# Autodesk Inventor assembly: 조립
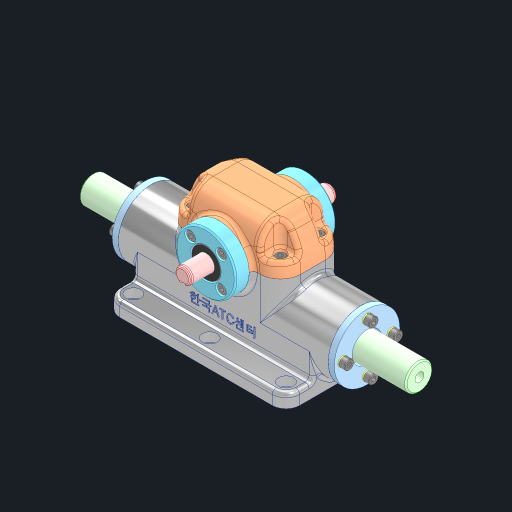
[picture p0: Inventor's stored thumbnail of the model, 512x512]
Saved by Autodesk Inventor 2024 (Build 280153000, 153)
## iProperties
Created: 2024-06
Part Number: 조립
Document SubType Name: Assembly
Designer: kh_501
Author: kh_501
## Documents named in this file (13)
- C:\Users\kh_501\Desktop\740604V1009\조립.iam
- C:\Users\kh_501\Desktop\740604V1009\본체.ipt
- C:\Users\kh_501\Desktop\740604V1009\깊은 홈 볼 베어링 6901\깊은 홈 볼 베어링 6901.ipt
- C:\Users\kh_501\Desktop\740604V1009\랙\랙.ipt
- C:\Users\kh_501\Desktop\740604V1009\베어링 커버\베어링 커버.ipt
- C:\Users\kh_501\Desktop\740604V1009\부시 커버\부시 커버.ipt
- C:\Users\kh_501\Desktop\740604V1009\스프링 와셔 M4\스프링 와셔 M4.ipt
- C:\Users\kh_501\Desktop\740604V1009\오일레스 부시\오일레스 부시.ipt
- C:\Users\kh_501\Desktop\740604V1009\오일실 12 22 7\오일실 12 22 7.ipt
- C:\Users\kh_501\Desktop\740604V1009\윗커버\윗커버.ipt
- C:\Users\kh_501\Desktop\740604V1009\육각 소켓 머리 볼트 M4x10\육각 소켓 머리 볼트 M4x10.ipt
- C:\Users\kh_501\Desktop\740604V1009\칼라\칼라.ipt
- C:\Users\kh_501\Desktop\740604V1009\피니언\피니언.ipt
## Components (1 placed, 1 different names)
1. 피니언:1
## Component patterns: 구성요소 패턴 1:2 (4 elements), 구성요소 패턴 2:2 (4 elements)
